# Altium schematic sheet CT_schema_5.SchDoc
size 302 x 256 mm
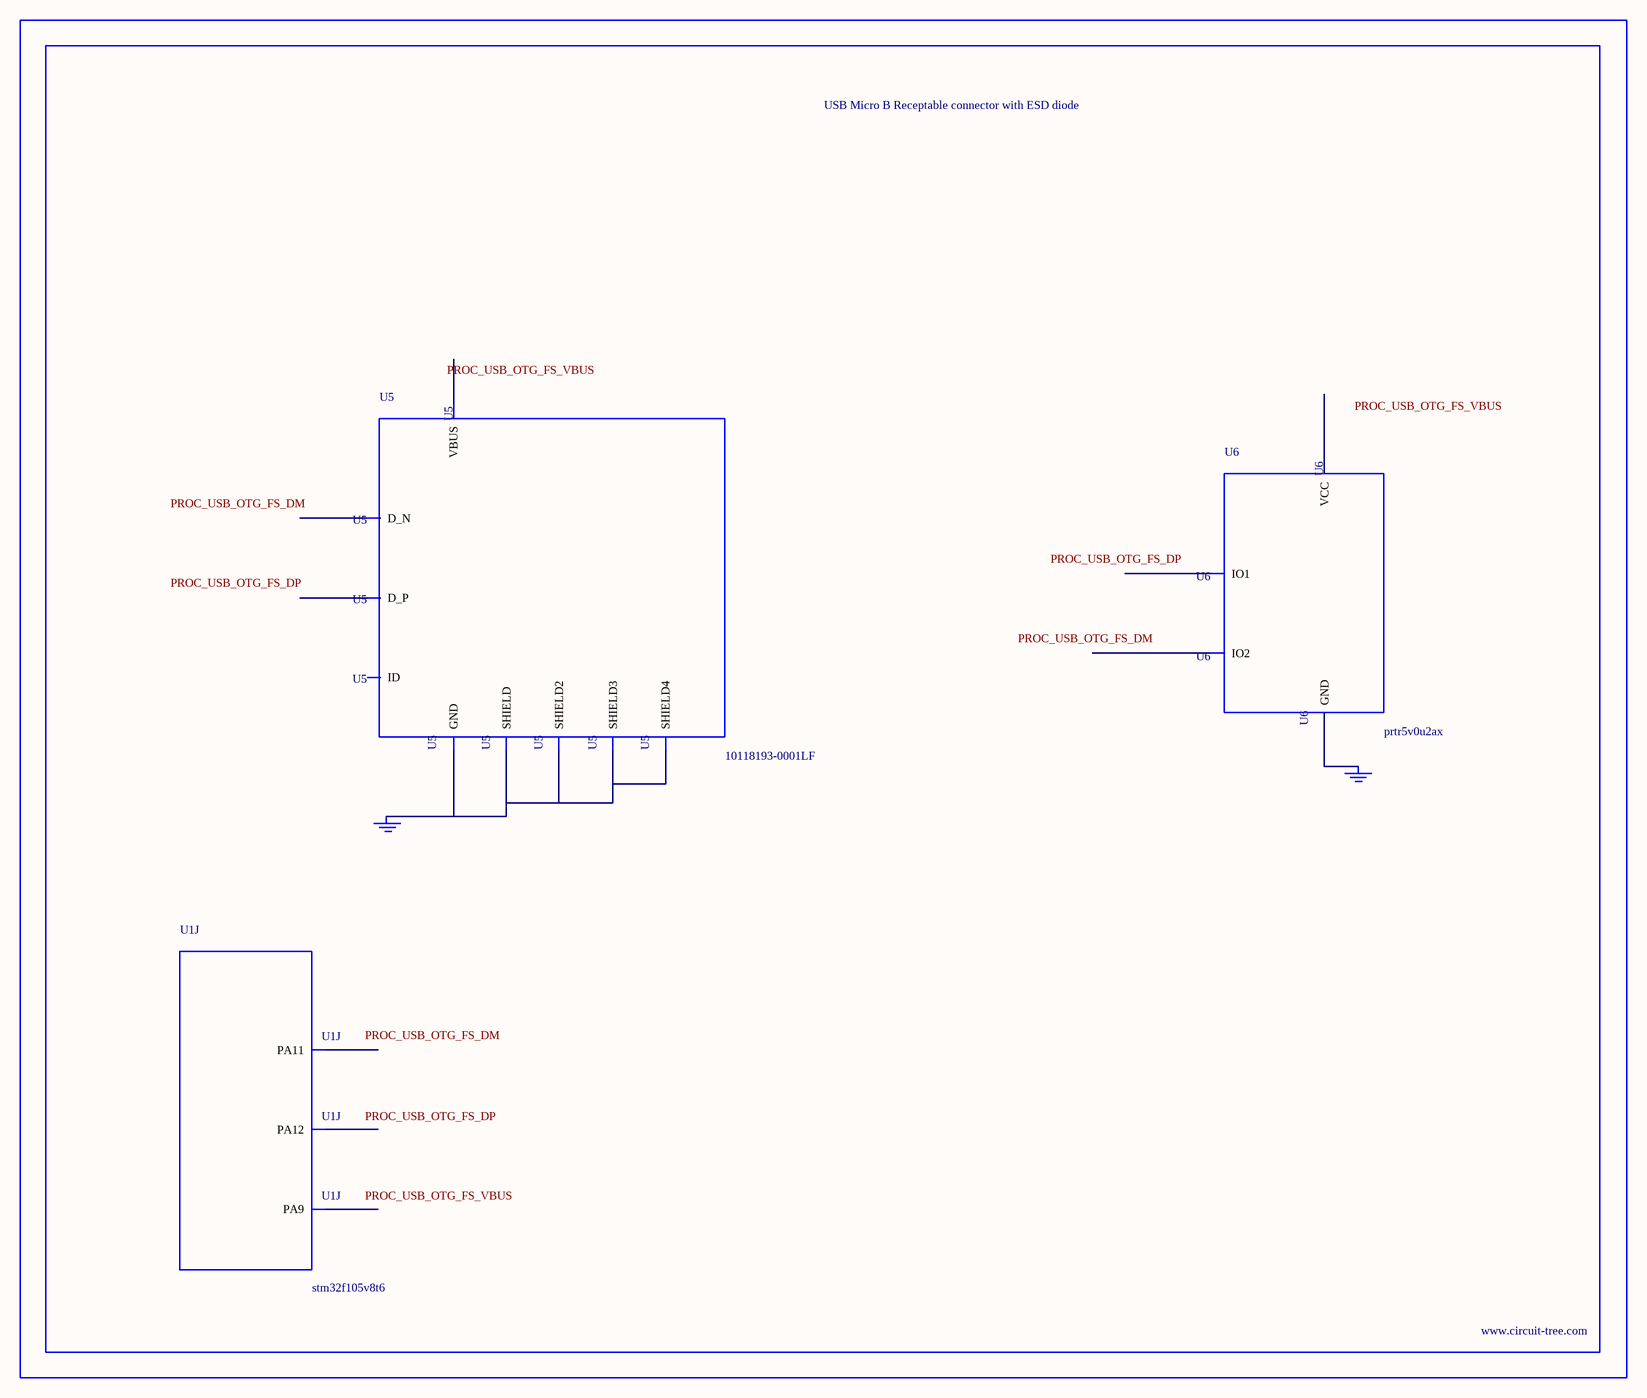
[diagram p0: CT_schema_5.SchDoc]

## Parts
BORDER4  (no value)
GND_INSTANCE_4_0  (no value)
GND_INSTANCE_4_1  (no value)
U1  stm32f105v8t6  [LQFP100]  (part J of 10)
U5  10118193-0001LF  [FCI_10118193-0001LF]
U6  prtr5v0u2ax  [SOT143B]

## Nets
NetGND_INSTANCE_4_0_0: GND_INSTANCE_4_0.0(GND) U5.5(GND) U5.6(SHIELD) U5.7(SHIELD2) U5.8(SHIELD3) U5.9(SHIELD4)
NetGND_INSTANCE_4_1_0: GND_INSTANCE_4_1.0(GND) U6.1(GND)

Not connected (* = marked no-connect by the designer): U1 68(PA9) 70(PA11) 71(PA12); U5 1(VBUS) 2(D_N) 3(D_P) 4(ID); U6 2(IO1) 3(IO2) 4(VCC)

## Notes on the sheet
- Labels drawn without touching a wire or pin: PROC_USB_OTG_FS_DM, PROC_USB_OTG_FS_DP, PROC_USB_OTG_FS_VBUS

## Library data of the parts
BORDER4 = BORDER_PAGE4
GND_INSTANCE_4_0 GND_INSTANCE_4_1 = GND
